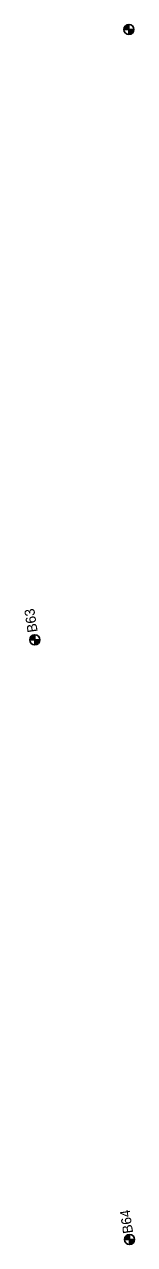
# Model space of a CAD drawing. Extents: x 345549 to 379569, y 127949 to 230467.
# Drawn here: x 359339 to 359448, y 164656 to 165868 of the extents above; entities that cross this region are included whole.
import ezdxf

# ---------------------------------------------------------------- set-up
doc = ezdxf.new("R2010")
doc.units = 0
doc.layers.add('E_SOIL_BORE1 [KAPUR_CADDS_LEVELS]', color=7, linetype='Continuous')
doc.layers.add('P_MARK', color=7, linetype='Continuous')

msp = doc.modelspace()

# ---------------------------------------------------------------- linework, layer by layer
at = {"layer": 'P_MARK'}
for p, q in [((359437.8, 165863.3), (359447.8, 165863.3)), ((359442.8, 165868.3), (359442.8, 165858.3)), ((359344.2, 165256.8), (359354.2, 165256.8)), ((359349.2, 165261.8), (359349.2, 165251.8)), ((359443.4, 164665.9), (359443.4, 164655.9)), ((359438.4, 164660.9), (359448.4, 164660.9))]:
    msp.add_line(p, q, dxfattribs=at)
for centre in [(359442.8, 165863.3), (359349.2, 165256.8), (359443.4, 164660.9)]:
    msp.add_circle(centre, 5, dxfattribs=at)
for centre, radius, start, end in [((359442.8, 165863.3), 4.5, 89.9869, 179.9869), ((359442.8, 165863.3), 4, 89.9869, 179.9869), ((359442.8, 165863.3), 3.5, 89.9869, 179.9869), ((359442.8, 165863.3), 3, 89.9869, 179.9869), ((359442.8, 165863.3), 2.5, 89.9869, 179.9869), ((359442.8, 165863.3), 2, 89.9869, 179.9869), ((359442.8, 165863.3), 1.5, 89.9869, 179.9869), ((359442.8, 165863.3), 1, 89.9869, 179.9869), ((359442.8, 165863.3), 0.5, 89.9869, 179.9869), ((359442.8, 165863.3), 4.5, 269.9869, 359.9869), ((359442.8, 165863.3), 4, 269.9869, 359.9869), ((359442.8, 165863.3), 3.5, 269.9869, 359.9869), ((359442.8, 165863.3), 3, 269.9869, 359.9869), ((359442.8, 165863.3), 2.5, 269.9869, 359.9869), ((359442.8, 165863.3), 2, 269.9869, 359.9869), ((359442.8, 165863.3), 1.5, 269.9869, 359.9869), ((359442.8, 165863.3), 1, 269.9869, 359.9869), ((359442.8, 165863.3), 0.5, 269.9869, 359.9869), ((359349.2, 165256.8), 4.5, 89.9869, 179.9869), ((359349.2, 165256.8), 4, 89.9869, 179.9869), ((359349.2, 165256.8), 3.5, 89.9869, 179.9869), ((359349.2, 165256.8), 3, 89.9869, 179.9869), ((359349.2, 165256.8), 2.5, 89.9869, 179.9869), ((359349.2, 165256.8), 2, 89.9869, 179.9869), ((359349.2, 165256.8), 1.5, 89.9869, 179.9869), ((359349.2, 165256.8), 1, 89.9869, 179.9869), ((359349.2, 165256.8), 0.5, 89.9869, 179.9869), ((359349.2, 165256.8), 4.5, 269.9869, 359.9869), ((359349.2, 165256.8), 4, 269.9869, 359.9869), ((359349.2, 165256.8), 3.5, 269.9869, 359.9869), ((359349.2, 165256.8), 3, 269.9869, 359.9869), ((359349.2, 165256.8), 2.5, 269.9869, 359.9869), ((359349.2, 165256.8), 2, 269.9869, 359.9869), ((359349.2, 165256.8), 1.5, 269.9869, 359.9869), ((359349.2, 165256.8), 1, 269.9869, 359.9869), ((359349.2, 165256.8), 0.5, 269.9869, 359.9869), ((359443.4, 164660.9), 4.5, 89.9869, 179.9869), ((359443.4, 164660.9), 4, 89.9869, 179.9869), ((359443.4, 164660.9), 3.5, 89.9869, 179.9869), ((359443.4, 164660.9), 3, 89.9869, 179.9869), ((359443.4, 164660.9), 2.5, 89.9869, 179.9869), ((359443.4, 164660.9), 2, 89.9869, 179.9869), ((359443.4, 164660.9), 1.5, 89.9869, 179.9869), ((359443.4, 164660.9), 1, 89.9869, 179.9869), ((359443.4, 164660.9), 0.5, 89.9869, 179.9869), ((359443.4, 164660.9), 4.5, 269.9869, 359.9869), ((359443.4, 164660.9), 4, 269.9869, 359.9869), ((359443.4, 164660.9), 3.5, 269.9869, 359.9869), ((359443.4, 164660.9), 3, 269.9869, 359.9869), ((359443.4, 164660.9), 2.5, 269.9869, 359.9869), ((359443.4, 164660.9), 2, 269.9869, 359.9869), ((359443.4, 164660.9), 1.5, 269.9869, 359.9869), ((359443.4, 164660.9), 1, 269.9869, 359.9869), ((359443.4, 164660.9), 0.5, 269.9869, 359.9869)]:
    msp.add_arc(centre, radius, start, end, dxfattribs=at)

# ---------------------------------------------------------------- texts
at = {"layer": 'E_SOIL_BORE1 [KAPUR_CADDS_LEVELS]'}
for s, p in [('B63', (359352.1, 165264.9)), ('B64', (359447, 164667.6))]:
    msp.add_text(s, height=10, rotation=98.5151, dxfattribs=at).set_placement(p)

doc.saveas('drawing.dxf')
